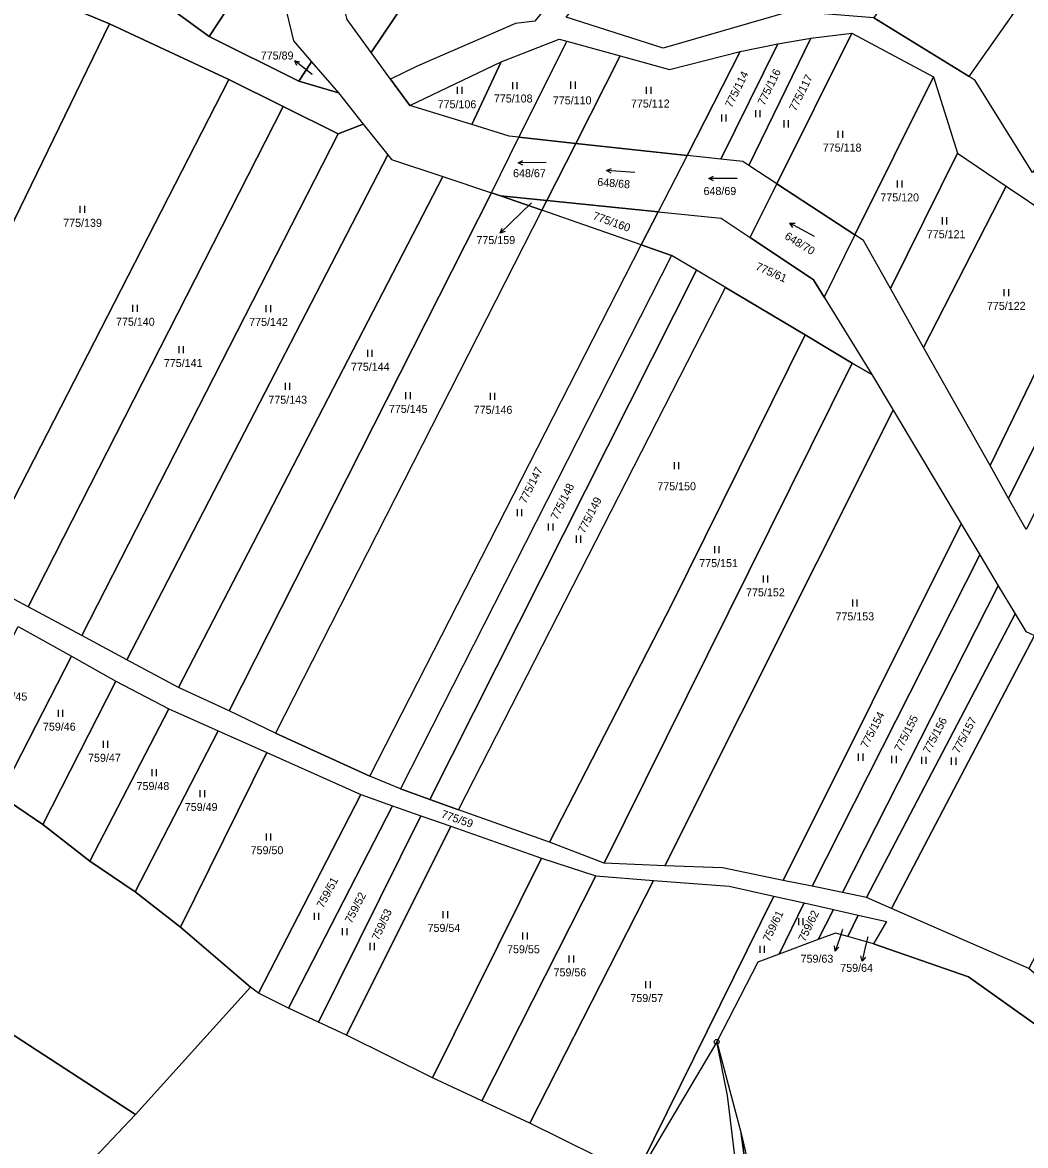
# Model space of a CAD drawing. Extents: x -654083 to -650132, y -1099819 to -1096699.
# Drawn here: x -653492.6 to -653279.3, y -1098231 to -1097992.4 of the extents above; entities that cross this region are included whole.
import ezdxf

# ---------------------------------------------------------------- set-up
doc = ezdxf.new("R2010")
doc.units = 0
for name, color, linetype in [('Geodetické body', 7, 'Continuous'), ('Obvody jako plochy', 7, 'Continuous'), ('Parcelní čísla', 7, 'Continuous'), ('Prvky pro prodl_ par_ č_', 7, 'Continuous'), ('Značky kultur', 7, 'Continuous')]:
    doc.layers.add(name, color=color, linetype=linetype)

msp = doc.modelspace()

# ---------------------------------------------------------------- linework, layer by layer
at = {"layer": 'Geodetické body'}
for radius in [0.5, 0.001]:
    msp.add_circle((-653345, -1098208.95), radius, dxfattribs=at)
at = {"layer": 'Obvody jako plochy'}
for points in [[(-653337.87, -1097879.12), (-653418.41, -1097998.78), (-653423.55, -1097991.72), (-653424, -1097990.03), (-653345.12, -1097872.11)], [(-653408.64, -1098001.67), (-653414.32, -1098004.39), (-653418.41, -1097998.78), (-653337.87, -1097879.12), (-653329.51, -1097886.88), (-653307.71, -1097896.81), (-653383.64, -1097992.11), (-653387.78, -1097992.62)], [(-653274.68, -1097936.55), (-653311.62, -1097991.38), (-653329.18, -1097990.01), (-653356.37, -1097997.84), (-653377, -1097991.28), (-653302.61, -1097902.5), (-653282.53, -1097923.86), (-653279.96, -1097933.3)], [(-653291.32, -1098003.86), (-653255.74, -1097953.38), (-653269.35, -1097939.83), (-653274.68, -1097936.55), (-653311.62, -1097991.38)], [(-653232.34, -1097965.52), (-653277.85, -1098024.22), (-653290.05, -1098004.68), (-653291.32, -1098003.86), (-653255.74, -1097953.38), (-653248.25, -1097960.84), (-653236.61, -1097962.12)], [(-653443.81, -1097959.64), (-653439.94, -1097975.63), (-653452.85, -1097995.35), (-653462.51, -1097988.32)], [(-653431.09, -1098000.73), (-653433.8, -1098004.82), (-653452.85, -1097995.35), (-653439.94, -1097975.63), (-653434.93, -1097996.3)], [(-653474.06, -1097992.64), (-653522.9, -1098093.01), (-653545.29, -1098066.46), (-653544.24, -1098064.55), (-653499, -1097982.28)], [(-653448.67, -1098004.49), (-653503.03, -1098110.31), (-653514.16, -1098104.36), (-653522.9, -1098093.01), (-653474.06, -1097992.64)], [(-653390.8, -1098000.73), (-653378.48, -1097995.93), (-653376.87, -1097996.37), (-653387.02, -1098016.78), (-653389.09, -1098016.56), (-653397.05, -1098014.09)], [(-653331.98, -1097996.91), (-653324.96, -1097995.69), (-653338.14, -1098022.75), (-653339.46, -1098021.89), (-653344.08, -1098021.39)], [(-653316.25, -1097994.63), (-653332.2, -1098026.64), (-653338.14, -1098022.75), (-653324.96, -1097995.69)], [(-653298.9, -1098003.91), (-653315.6, -1098037.52), (-653332.2, -1098026.64), (-653316.25, -1097994.63)], [(-653376.87, -1097996.37), (-653365.48, -1097999.5), (-653374.95, -1098018.08), (-653387.02, -1098016.78)], [(-653355, -1098002.39), (-653340, -1097998.55), (-653351.29, -1098020.62), (-653374.95, -1098018.08), (-653365.48, -1097999.5)], [(-653340, -1097998.55), (-653331.98, -1097996.91), (-653344.08, -1098021.39), (-653351.29, -1098020.62)], [(-653425.36, -1098007.36), (-653433.8, -1098004.82), (-653431.09, -1098000.73)], [(-653410.22, -1098010.01), (-653390.8, -1098000.73), (-653397.05, -1098014.09)], [(-653491.36, -1098116.55), (-653503.03, -1098110.31), (-653448.67, -1098004.49), (-653437.16, -1098010.24)], [(-653298.9, -1098003.91), (-653293.82, -1098020.17), (-653308.05, -1098048.88), (-653313.77, -1098038.72), (-653315.6, -1098037.52)], [(-653479.94, -1098122.66), (-653491.36, -1098116.55), (-653437.16, -1098010.24), (-653425.49, -1098016.06)], [(-653414.9, -1098020.52), (-653470.35, -1098127.79), (-653479.94, -1098122.66), (-653425.49, -1098016.06), (-653420.12, -1098013.95)], [(-653374.95, -1098018.08), (-653381.13, -1098030.2), (-653390.96, -1098029.21), (-653392.89, -1098028.57), (-653387.02, -1098016.78)], [(-653374.95, -1098018.08), (-653351.29, -1098020.62), (-653357.41, -1098032.59), (-653381.13, -1098030.2)], [(-653283.44, -1098027.14), (-653301, -1098061.42), (-653308.05, -1098048.88), (-653293.82, -1098020.17)], [(-653403.21, -1098025.12), (-653459.37, -1098133.66), (-653470.35, -1098127.79), (-653414.9, -1098020.52), (-653414.14, -1098021.47)], [(-653344.06, -1098033.94), (-653337.9, -1098038.07), (-653332.2, -1098026.64), (-653338.14, -1098022.75), (-653339.46, -1098021.89), (-653344.08, -1098021.39), (-653351.29, -1098020.62), (-653357.41, -1098032.59)], [(-653448.64, -1098138.64), (-653459.37, -1098133.66), (-653403.21, -1098025.12), (-653392.89, -1098028.57)], [(-653315.6, -1098037.52), (-653322.18, -1098050.75), (-653324.45, -1098047.07), (-653337.9, -1098038.07), (-653332.2, -1098026.64)], [(-653264.25, -1098040.07), (-653286.85, -1098086.54), (-653301, -1098061.42), (-653283.44, -1098027.14)], [(-653392.89, -1098028.57), (-653390.96, -1098029.21), (-653382.18, -1098032.27), (-653438.8, -1098143.39), (-653448.64, -1098138.64)], [(-653381.13, -1098030.2), (-653382.18, -1098032.27), (-653390.96, -1098029.21)], [(-653357.41, -1098032.59), (-653361.02, -1098039.65), (-653382.18, -1098032.27), (-653381.13, -1098030.2)], [(-653361.02, -1098039.65), (-653382.18, -1098032.27), (-653438.8, -1098143.39), (-653418.76, -1098152.53)], [(-653337.9, -1098038.07), (-653324.45, -1098047.07), (-653322.18, -1098050.75), (-653312.04, -1098067.2), (-653316.17, -1098064.74), (-653326.19, -1098058.78), (-653343.12, -1098048.71), (-653349.32, -1098045.02), (-653354.59, -1098041.89), (-653361.02, -1098039.65), (-653357.41, -1098032.59), (-653344.06, -1098033.94)], [(-653354.59, -1098041.89), (-653412.2, -1098155.23), (-653418.76, -1098152.53), (-653361.02, -1098039.65)], [(-653264.25, -1098040.07), (-653258.36, -1098044.1), (-653282.94, -1098093.51), (-653286.85, -1098086.54)], [(-653349.32, -1098045.02), (-653354.59, -1098041.89), (-653412.2, -1098155.23), (-653405.94, -1098157.48)], [(-653526.47, -1098135.95), (-653518.87, -1098141.6), (-653508.05, -1098149.35), (-653498.93, -1098155.64), (-653497.41, -1098156.63), (-653488.24, -1098162.8), (-653478.25, -1098170.57), (-653468.63, -1098177.08), (-653458.96, -1098184.59), (-653444.09, -1098197.38), (-653468.56, -1098224.39), (-653510.59, -1098197.1), (-653538.11, -1098179.34), (-653569.01, -1098159.89), (-653542.28, -1098133.96), (-653582.6, -1098103.32), (-653551.01, -1098074.32), (-653559.78, -1098061.29), (-653598.42, -1098044.74), (-653590.78, -1098045.19), (-653559.18, -1098057.02), (-653547.07, -1098069.66), (-653543, -1098124.32), (-653539.45, -1098126.81)], [(-653343.12, -1098048.71), (-653349.32, -1098045.02), (-653405.94, -1098157.48), (-653399.87, -1098159.66)], [(-653252.87, -1098047.8), (-653279.24, -1098100.09), (-653282.94, -1098093.51), (-653258.36, -1098044.1)], [(-653326.19, -1098058.78), (-653354.54, -1098115.97), (-653380.57, -1098166.58), (-653399.87, -1098159.66), (-653343.12, -1098048.71)], [(-653316.17, -1098064.74), (-653368.93, -1098171.02), (-653380.57, -1098166.58), (-653354.54, -1098115.97), (-653326.19, -1098058.78)], [(-653307.45, -1098074.78), (-653355.99, -1098171.56), (-653368.93, -1098171.02), (-653316.17, -1098064.74), (-653312.04, -1098067.2)], [(-653307.45, -1098074.78), (-653293.04, -1098098.89), (-653330.85, -1098174.66), (-653343.74, -1098171.99), (-653355.99, -1098171.56)], [(-653293.04, -1098098.89), (-653289.08, -1098105.51), (-653324.7, -1098175.91), (-653330.85, -1098174.66)], [(-653289.08, -1098105.51), (-653285.15, -1098112.06), (-653318.28, -1098177.23), (-653324.7, -1098175.91)], [(-653285.15, -1098112.06), (-653281.57, -1098118.02), (-653313.14, -1098178.29), (-653318.28, -1098177.23)], [(-653281.57, -1098118.02), (-653279.31, -1098121.79), (-653277.44, -1098122.65), (-653307.83, -1098180.61), (-653313.14, -1098178.29)], [(-653482.17, -1098127.04), (-653497.41, -1098156.63), (-653498.93, -1098155.64), (-653508.05, -1098149.35), (-653493.48, -1098120.72)], [(-653256.22, -1098132.47), (-653247.61, -1098134.08), (-653278.65, -1098193.38), (-653307.83, -1098180.61), (-653277.44, -1098122.65)], [(-653482.17, -1098127.04), (-653472.69, -1098132.34), (-653488.24, -1098162.8), (-653497.41, -1098156.63)], [(-653472.69, -1098132.34), (-653461.42, -1098138.22), (-653478.25, -1098170.57), (-653488.24, -1098162.8)], [(-653451, -1098142.87), (-653468.63, -1098177.08), (-653478.25, -1098170.57), (-653461.42, -1098138.22)], [(-653440.64, -1098147.5), (-653458.96, -1098184.59), (-653468.63, -1098177.08), (-653451, -1098142.87)], [(-653440.64, -1098147.5), (-653420.66, -1098156.42), (-653442.37, -1098198.6), (-653444.09, -1098197.38), (-653458.96, -1098184.59)], [(-653435.99, -1098201.81), (-653442.37, -1098198.6), (-653420.66, -1098156.42), (-653413.9, -1098158.8)], [(-653429.67, -1098204.79), (-653435.99, -1098201.81), (-653413.9, -1098158.8), (-653407.86, -1098160.93)], [(-653401.5, -1098163.17), (-653423.68, -1098207.59), (-653429.67, -1098204.79), (-653407.86, -1098160.93)], [(-653382.27, -1098169.95), (-653405.39, -1098216.6), (-653423.68, -1098207.59), (-653401.5, -1098163.17)], [(-653370.67, -1098173.73), (-653394.94, -1098221.48), (-653405.39, -1098216.6), (-653382.27, -1098169.95)], [(-653358.4, -1098174.67), (-653384.71, -1098226.25), (-653394.94, -1098221.48), (-653370.67, -1098173.73)], [(-653332.88, -1098178.02), (-653364, -1098241.1), (-653363.54, -1098236.76), (-653384.71, -1098226.25), (-653358.4, -1098174.67), (-653342.34, -1098175.9)], [(-653336.25, -1098192.05), (-653345, -1098208.95), (-653364, -1098241.1), (-653332.88, -1098178.02), (-653326.43, -1098179.47), (-653331.7, -1098190.34)], [(-653323.45, -1098187.25), (-653331.7, -1098190.34), (-653326.43, -1098179.47), (-653320.16, -1098180.87)], [(-653317.13, -1098186.57), (-653319.71, -1098185.85), (-653323.45, -1098187.25), (-653320.16, -1098180.87), (-653314.95, -1098182.04)], [(-653311.64, -1098188.12), (-653317.13, -1098186.57), (-653314.95, -1098182.04), (-653308.89, -1098183.4)], [(-653510.59, -1098197.1), (-653468.56, -1098224.39), (-653476.06, -1098232.31), (-653502.41, -1098257.19), (-653546.7, -1098228.92)], [(-653356.59, -1098259.77), (-653356.48, -1098252.09), (-653347.19, -1098269.67), (-653338.79, -1098252.38), (-653342.69, -1098220.4), (-653345, -1098208.95), (-653364, -1098241.1), (-653367.61, -1098264.53), (-653355.28, -1098276.65)], [(-653345, -1098208.95), (-653339.77, -1098228.47), (-653336.9, -1098249.8), (-653323.1, -1098284.44), (-653320.45, -1098285.64), (-653304.46, -1098306.2), (-653270.85, -1098343.91), (-653272.78, -1098346.99), (-653291.48, -1098328.46), (-653295.76, -1098319.24), (-653308.43, -1098309.28), (-653330.44, -1098285.01), (-653338.79, -1098252.38), (-653342.69, -1098220.4)], [(-653323.1, -1098284.44), (-653336.9, -1098249.8), (-653339.77, -1098228.47), (-653333.68, -1098254.4), (-653323.63, -1098281.56), (-653320.45, -1098285.64)]]:
    msp.add_lwpolyline(points, close=True, dxfattribs=at)
for points in [[(-653496.78, -1097959.19), (-653491.2, -1097972.7), (-653483.03, -1097982.43), (-653472.83, -1097986.43), (-653462.51, -1097988.32), (-653452.85, -1097995.35), (-653433.8, -1098004.82), (-653425.36, -1098007.36), (-653420.12, -1098013.95), (-653425.49, -1098016.06), (-653437.16, -1098010.24), (-653448.67, -1098004.49), (-653474.06, -1097992.64), (-653499, -1097982.28)], [(-653439.94, -1097975.63), (-653434.93, -1097996.3), (-653431.09, -1098000.73), (-653425.36, -1098007.36), (-653420.12, -1098013.95), (-653414.9, -1098020.52), (-653414.14, -1098021.47), (-653403.21, -1098025.12), (-653392.89, -1098028.57), (-653387.02, -1098016.78), (-653389.09, -1098016.56), (-653397.05, -1098014.09), (-653410.22, -1098010.01), (-653414.32, -1098004.39), (-653418.41, -1097998.78), (-653423.55, -1097991.72)], [(-653329.18, -1097990.01), (-653356.37, -1097997.84), (-653377, -1097991.28)], [(-653277.85, -1098024.22), (-653290.05, -1098004.68), (-653291.32, -1098003.86), (-653311.62, -1097991.38)], [(-653383.64, -1097992.11), (-653387.78, -1097992.62), (-653408.64, -1098001.67), (-653414.32, -1098004.39), (-653410.22, -1098010.01), (-653390.8, -1098000.73), (-653378.48, -1097995.93), (-653376.87, -1097996.37), (-653365.48, -1097999.5), (-653355, -1098002.39), (-653340, -1097998.55), (-653331.98, -1097996.91), (-653324.96, -1097995.69), (-653316.25, -1097994.63), (-653298.9, -1098003.91), (-653293.82, -1098020.17), (-653283.44, -1098027.14), (-653264.25, -1098040.07)], [(-653279.24, -1098100.09), (-653282.94, -1098093.51), (-653286.85, -1098086.54), (-653301, -1098061.42), (-653308.05, -1098048.88), (-653313.77, -1098038.72), (-653315.6, -1098037.52), (-653322.18, -1098050.75), (-653312.04, -1098067.2), (-653307.45, -1098074.78), (-653293.04, -1098098.89), (-653289.08, -1098105.51), (-653285.15, -1098112.06), (-653281.57, -1098118.02), (-653279.31, -1098121.79)], [(-653220.95, -1098256.03), (-653255.32, -1098213.68), (-653278.65, -1098193.38), (-653307.83, -1098180.61), (-653313.14, -1098178.29), (-653318.28, -1098177.23), (-653324.7, -1098175.91), (-653330.85, -1098174.66), (-653343.74, -1098171.99), (-653355.99, -1098171.56), (-653368.93, -1098171.02), (-653380.57, -1098166.58), (-653399.87, -1098159.66), (-653405.94, -1098157.48), (-653412.2, -1098155.23), (-653418.76, -1098152.53), (-653438.8, -1098143.39), (-653448.64, -1098138.64), (-653459.37, -1098133.66), (-653470.35, -1098127.79), (-653479.94, -1098122.66), (-653491.36, -1098116.55), (-653503.03, -1098110.31)], [(-653493.48, -1098120.72), (-653482.17, -1098127.04), (-653472.69, -1098132.34), (-653461.42, -1098138.22), (-653451, -1098142.87), (-653440.64, -1098147.5), (-653420.66, -1098156.42), (-653413.9, -1098158.8), (-653407.86, -1098160.93), (-653401.5, -1098163.17), (-653382.27, -1098169.95), (-653370.67, -1098173.73), (-653358.4, -1098174.67), (-653342.34, -1098175.9), (-653332.88, -1098178.02), (-653326.43, -1098179.47), (-653320.16, -1098180.87), (-653314.95, -1098182.04), (-653308.89, -1098183.4), (-653311.64, -1098188.12), (-653291.44, -1098195.15), (-653273.74, -1098207.76), (-653248.25, -1098237.42)], [(-653248.25, -1098237.42), (-653273.74, -1098207.76), (-653291.44, -1098195.15), (-653311.64, -1098188.12), (-653317.13, -1098186.57), (-653319.71, -1098185.85), (-653323.45, -1098187.25), (-653331.7, -1098190.34), (-653336.25, -1098192.05), (-653345, -1098208.95), (-653339.77, -1098228.47), (-653333.68, -1098254.4)], [(-653363.54, -1098236.76), (-653384.71, -1098226.25), (-653394.94, -1098221.48), (-653405.39, -1098216.6), (-653423.68, -1098207.59), (-653429.67, -1098204.79), (-653435.99, -1098201.81), (-653442.37, -1098198.6), (-653444.09, -1098197.38), (-653468.56, -1098224.39), (-653476.06, -1098232.31)]]:
    msp.add_lwpolyline(points, dxfattribs=at)
at = {"layer": 'Prvky pro prodl_ par_ č_'}
for p, q in [((-653432.33, -1098002.37), (-653434.68, -1098000.51)), ((-653430.99, -1098003.43), (-653432.33, -1098002.37)), ((-653384.39, -1098030.71), (-653388.84, -1098035.03)), ((-653388.84, -1098035.03), (-653390.99, -1098037.12)), ((-653318.85, -1098186.84), (-653319.82, -1098189.68)), ((-653318.26, -1098185.09), (-653318.85, -1098186.84)), ((-653312.89, -1098186.64), (-653313.4, -1098188.89)), ((-653313.4, -1098188.89), (-653314.06, -1098191.82))]:
    msp.add_line(p, q, dxfattribs=at)
for points in [[(-653434.21, -1098001.52), (-653434.68, -1098000.51), (-653433.59, -1098000.74)], [(-653389.93, -1098036.78), (-653390.99, -1098037.12), (-653390.62, -1098036.06)], [(-653319.02, -1098188.89), (-653319.82, -1098189.68), (-653319.97, -1098188.57)], [(-653313.35, -1098190.95), (-653314.06, -1098191.82), (-653314.33, -1098190.73)]]:
    msp.add_lwpolyline(points, dxfattribs=at)
at = {"layer": 'Značky kultur'}
for p, q in [((-653388.43, -1098005.07), (-653388.43, -1098006.57)), ((-653387.41, -1098006.57), (-653387.41, -1098005.07)), ((-653376.04, -1098004.95), (-653376.04, -1098006.45)), ((-653375.02, -1098006.45), (-653375.02, -1098004.95)), ((-653400.15, -1098006.05), (-653400.15, -1098007.55)), ((-653399.12, -1098007.55), (-653399.12, -1098006.05)), ((-653359.97, -1098006.02), (-653359.97, -1098007.52)), ((-653358.95, -1098007.52), (-653358.95, -1098006.02)), ((-653343.98, -1098011.94), (-653343.98, -1098013.44)), ((-653342.95, -1098013.44), (-653342.95, -1098011.94)), ((-653336.78, -1098011), (-653336.78, -1098012.5)), ((-653335.76, -1098012.5), (-653335.76, -1098011)), ((-653330.73, -1098013.17), (-653330.73, -1098014.67)), ((-653329.7, -1098014.67), (-653329.7, -1098013.17)), ((-653319.23, -1098015.38), (-653319.23, -1098016.88)), ((-653318.2, -1098016.88), (-653318.2, -1098015.38)), ((-653381.21, -1098022.1), (-653387.21, -1098022.22)), ((-653362.41, -1098024.26), (-653368.39, -1098023.82)), ((-653340.64, -1098025.51), (-653346.64, -1098025.53)), ((-653306.63, -1098025.96), (-653306.63, -1098027.46)), ((-653305.6, -1098027.46), (-653305.6, -1098025.96)), ((-653480.34, -1098031.36), (-653480.34, -1098032.86)), ((-653479.32, -1098032.86), (-653479.32, -1098031.36)), ((-653297.08, -1098033.77), (-653297.08, -1098035.27)), ((-653296.06, -1098035.27), (-653296.06, -1098033.77)), ((-653324.19, -1098037.88), (-653329.45, -1098035.02)), ((-653283.94, -1098049.01), (-653283.94, -1098050.51)), ((-653282.92, -1098050.51), (-653282.92, -1098049.01)), ((-653469.16, -1098052.39), (-653469.16, -1098053.89)), ((-653468.14, -1098053.89), (-653468.14, -1098052.39)), ((-653440.82, -1098052.43), (-653440.82, -1098053.93)), ((-653439.8, -1098053.93), (-653439.8, -1098052.43)), ((-653459.33, -1098061.15), (-653459.33, -1098062.65)), ((-653458.31, -1098062.65), (-653458.31, -1098061.15)), ((-653419.25, -1098061.95), (-653419.25, -1098063.45)), ((-653418.22, -1098063.45), (-653418.22, -1098061.95)), ((-653436.72, -1098068.96), (-653436.72, -1098070.46)), ((-653435.7, -1098070.46), (-653435.7, -1098068.96)), ((-653411.14, -1098070.91), (-653411.14, -1098072.41)), ((-653410.11, -1098072.41), (-653410.11, -1098070.91)), ((-653393.15, -1098071.09), (-653393.15, -1098072.59)), ((-653392.12, -1098072.59), (-653392.12, -1098071.09)), ((-653354.06, -1098085.82), (-653354.06, -1098087.32)), ((-653353.04, -1098087.32), (-653353.04, -1098085.82)), ((-653387.41, -1098095.77), (-653387.41, -1098097.27)), ((-653386.39, -1098097.27), (-653386.39, -1098095.77)), ((-653380.81, -1098098.82), (-653380.81, -1098100.32)), ((-653379.79, -1098100.32), (-653379.79, -1098098.82)), ((-653374.9, -1098101.41), (-653374.9, -1098102.91)), ((-653373.88, -1098102.91), (-653373.88, -1098101.41)), ((-653345.48, -1098103.67), (-653345.48, -1098105.17)), ((-653344.45, -1098105.17), (-653344.45, -1098103.67)), ((-653335.15, -1098109.88), (-653335.15, -1098111.38)), ((-653334.12, -1098111.38), (-653334.12, -1098109.88)), ((-653316.14, -1098114.99), (-653316.14, -1098116.49)), ((-653315.11, -1098116.49), (-653315.11, -1098114.99)), ((-653484.99, -1098138.42), (-653484.99, -1098139.92)), ((-653483.96, -1098139.92), (-653483.96, -1098138.42)), ((-653475.44, -1098145.03), (-653475.44, -1098146.53)), ((-653474.42, -1098146.53), (-653474.42, -1098145.03)), ((-653314.89, -1098147.74), (-653314.89, -1098149.24)), ((-653313.86, -1098149.24), (-653313.86, -1098147.74)), ((-653307.81, -1098148.23), (-653307.81, -1098149.73)), ((-653306.79, -1098149.73), (-653306.79, -1098148.23)), ((-653301.46, -1098148.42), (-653301.46, -1098149.92)), ((-653300.44, -1098149.92), (-653300.44, -1098148.42)), ((-653295.13, -1098148.58), (-653295.13, -1098150.08)), ((-653294.1, -1098150.08), (-653294.1, -1098148.58)), ((-653465.06, -1098151.03), (-653465.06, -1098152.53)), ((-653464.04, -1098152.53), (-653464.04, -1098151.03)), ((-653454.84, -1098155.5), (-653454.84, -1098157)), ((-653453.82, -1098157), (-653453.82, -1098155.5)), ((-653440.77, -1098164.68), (-653440.77, -1098166.18)), ((-653439.74, -1098166.18), (-653439.74, -1098164.68)), ((-653430.58, -1098181.58), (-653430.58, -1098183.08)), ((-653429.56, -1098183.08), (-653429.56, -1098181.58)), ((-653403.19, -1098181.18), (-653403.19, -1098182.68)), ((-653402.17, -1098182.68), (-653402.17, -1098181.18)), ((-653424.58, -1098184.82), (-653424.58, -1098186.32)), ((-653423.56, -1098186.32), (-653423.56, -1098184.82)), ((-653327.62, -1098182.71), (-653327.62, -1098184.21)), ((-653326.59, -1098184.21), (-653326.59, -1098182.71)), ((-653386.25, -1098185.72), (-653386.25, -1098187.22)), ((-653385.22, -1098187.22), (-653385.22, -1098185.72)), ((-653418.72, -1098187.96), (-653418.72, -1098189.46)), ((-653417.7, -1098189.46), (-653417.7, -1098187.96)), ((-653335.83, -1098188.58), (-653335.83, -1098190.08)), ((-653334.81, -1098190.08), (-653334.81, -1098188.58)), ((-653376.41, -1098190.62), (-653376.41, -1098192.12)), ((-653375.39, -1098192.12), (-653375.39, -1098190.62)), ((-653360.11, -1098196.07), (-653360.11, -1098197.57)), ((-653359.08, -1098197.57), (-653359.08, -1098196.07))]:
    msp.add_line(p, q, dxfattribs=at)
for points in [[(-653386.2, -1098022.7), (-653387.21, -1098022.22), (-653386.22, -1098021.7)], [(-653367.43, -1098024.39), (-653368.39, -1098023.82), (-653367.36, -1098023.39)], [(-653345.64, -1098026.03), (-653346.64, -1098025.53), (-653345.64, -1098025.03)], [(-653328.82, -1098035.93), (-653329.45, -1098035.02), (-653328.34, -1098035.05)]]:
    msp.add_lwpolyline(points, dxfattribs=at)

# ---------------------------------------------------------------- texts
at = {"layer": 'Parcelní čísla'}
for s, height, p in [('775/89', 0.1, (-653430.99, -1098003.43)), ('775/108', 1.7, (-653392.36, -1098009.38)), ('775/110', 1.7, (-653379.82, -1098009.77)), ('775/106', 1.7, (-653404.31, -1098010.61)), ('775/112', 1.7, (-653363.22, -1098010.45)), ('775/118', 1.7, (-653322.44, -1098019.81)), ('648/67', 1.7, (-653388.28, -1098025.25)), ('648/69', 1.7, (-653347.79, -1098029.04)), ('775/120', 1.7, (-653310.21, -1098030.39)), ('775/139', 1.7, (-653483.9, -1098035.8)), ('775/121', 1.7, (-653300.33, -1098038.21)), ('775/122', 1.7, (-653287.55, -1098053.44)), ('775/140', 1.7, (-653472.68, -1098056.82)), ('775/142', 1.7, (-653444.37, -1098056.86)), ('775/141', 1.7, (-653462.51, -1098065.58)), ('775/144', 1.7, (-653422.74, -1098066.38)), ('775/143', 1.7, (-653440.29, -1098073.39)), ('775/145', 1.7, (-653414.67, -1098075.34)), ('775/146', 1.7, (-653396.64, -1098075.53)), ('775/150', 1.7, (-653357.62, -1098091.78)), ('775/151', 1.7, (-653348.7, -1098108.1)), ('775/152', 1.7, (-653338.75, -1098114.31)), ('775/153', 1.7, (-653319.74, -1098119.42)), ('759/45', 1.7, (-653498.49, -1098136.45)), ('759/46', 1.7, (-653488.21, -1098142.85)), ('759/47', 1.7, (-653478.62, -1098149.47)), ('759/48', 1.7, (-653468.31, -1098155.47)), ('759/49', 1.7, (-653458.06, -1098159.93)), ('759/50', 1.7, (-653444.06, -1098169.11)), ('759/54', 1.7, (-653406.45, -1098185.61)), ('759/55', 1.7, (-653389.55, -1098190.15)), ('759/56', 1.7, (-653379.67, -1098195.06)), ('759/57', 1.7, (-653363.34, -1098200.51))]:
    msp.add_text(s, height=height, dxfattribs=at).set_placement(p)
for s, height, rotation, p in [('775/114', 1.7, 63.693, (-653341.81, -1098010.64)), ('775/116', 1.7, 64.224, (-653334.87, -1098010.15)), ('775/117', 1.7, 63.684, (-653328.17, -1098011.35)), ('648/68', 1.7, 355.23, (-653370.42, -1098027.07)), ('775/159', 0.1, 341.478, (-653384.39, -1098030.71)), ('775/160', 1.7, 340.344, (-653371.46, -1098034.14)), ('648/70', 1.7, 328.419, (-653330.71, -1098038.22)), ('775/61', 1.7, 335.619, (-653336.9, -1098044.8)), ('775/147', 1.7, 63.639, (-653385.56, -1098094.73)), ('775/148', 1.7, 63.369, (-653378.89, -1098098.19)), ('775/149', 1.7, 63.018, (-653373.1, -1098101.09)), ('775/154', 1.7, 62.676, (-653313.01, -1098146.71)), ('775/155', 1.7, 63.108, (-653305.82, -1098147.46)), ('775/156', 1.7, 62.289, (-653299.76, -1098147.86)), ('775/157', 1.7, 62.172, (-653293.5, -1098147.83)), ('775/59', 1.7, 340.866, (-653403.7, -1098161.26)), ('759/51', 1.7, 62.064, (-653428.64, -1098180.71)), ('759/52', 1.7, 62.658, (-653422.64, -1098183.93)), ('759/53', 1.7, 65.529, (-653416.85, -1098187.55)), ('759/61', 1.7, 63.882, (-653333.79, -1098187.86)), ('759/62', 1.7, 63.99, (-653326.23, -1098187.82)), ('759/63', 0.1, 63.711, (-653318.26, -1098185.09)), ('759/64', 0.1, 65.295, (-653312.89, -1098186.64))]:
    msp.add_text(s, height=height, rotation=rotation, dxfattribs=at).set_placement(p)
at = {"layer": 'Prvky pro prodl_ par_ č_'}
for s, p in [('775/89', (-653441.91, -1098000.25)), ('775/159', (-653396.06, -1098039.46)), ('759/63', (-653327.16, -1098192.16)), ('759/64', (-653318.73, -1098194.1))]:
    msp.add_text(s, height=1.7, dxfattribs=at).set_placement(p)

doc.saveas('drawing.dxf')
